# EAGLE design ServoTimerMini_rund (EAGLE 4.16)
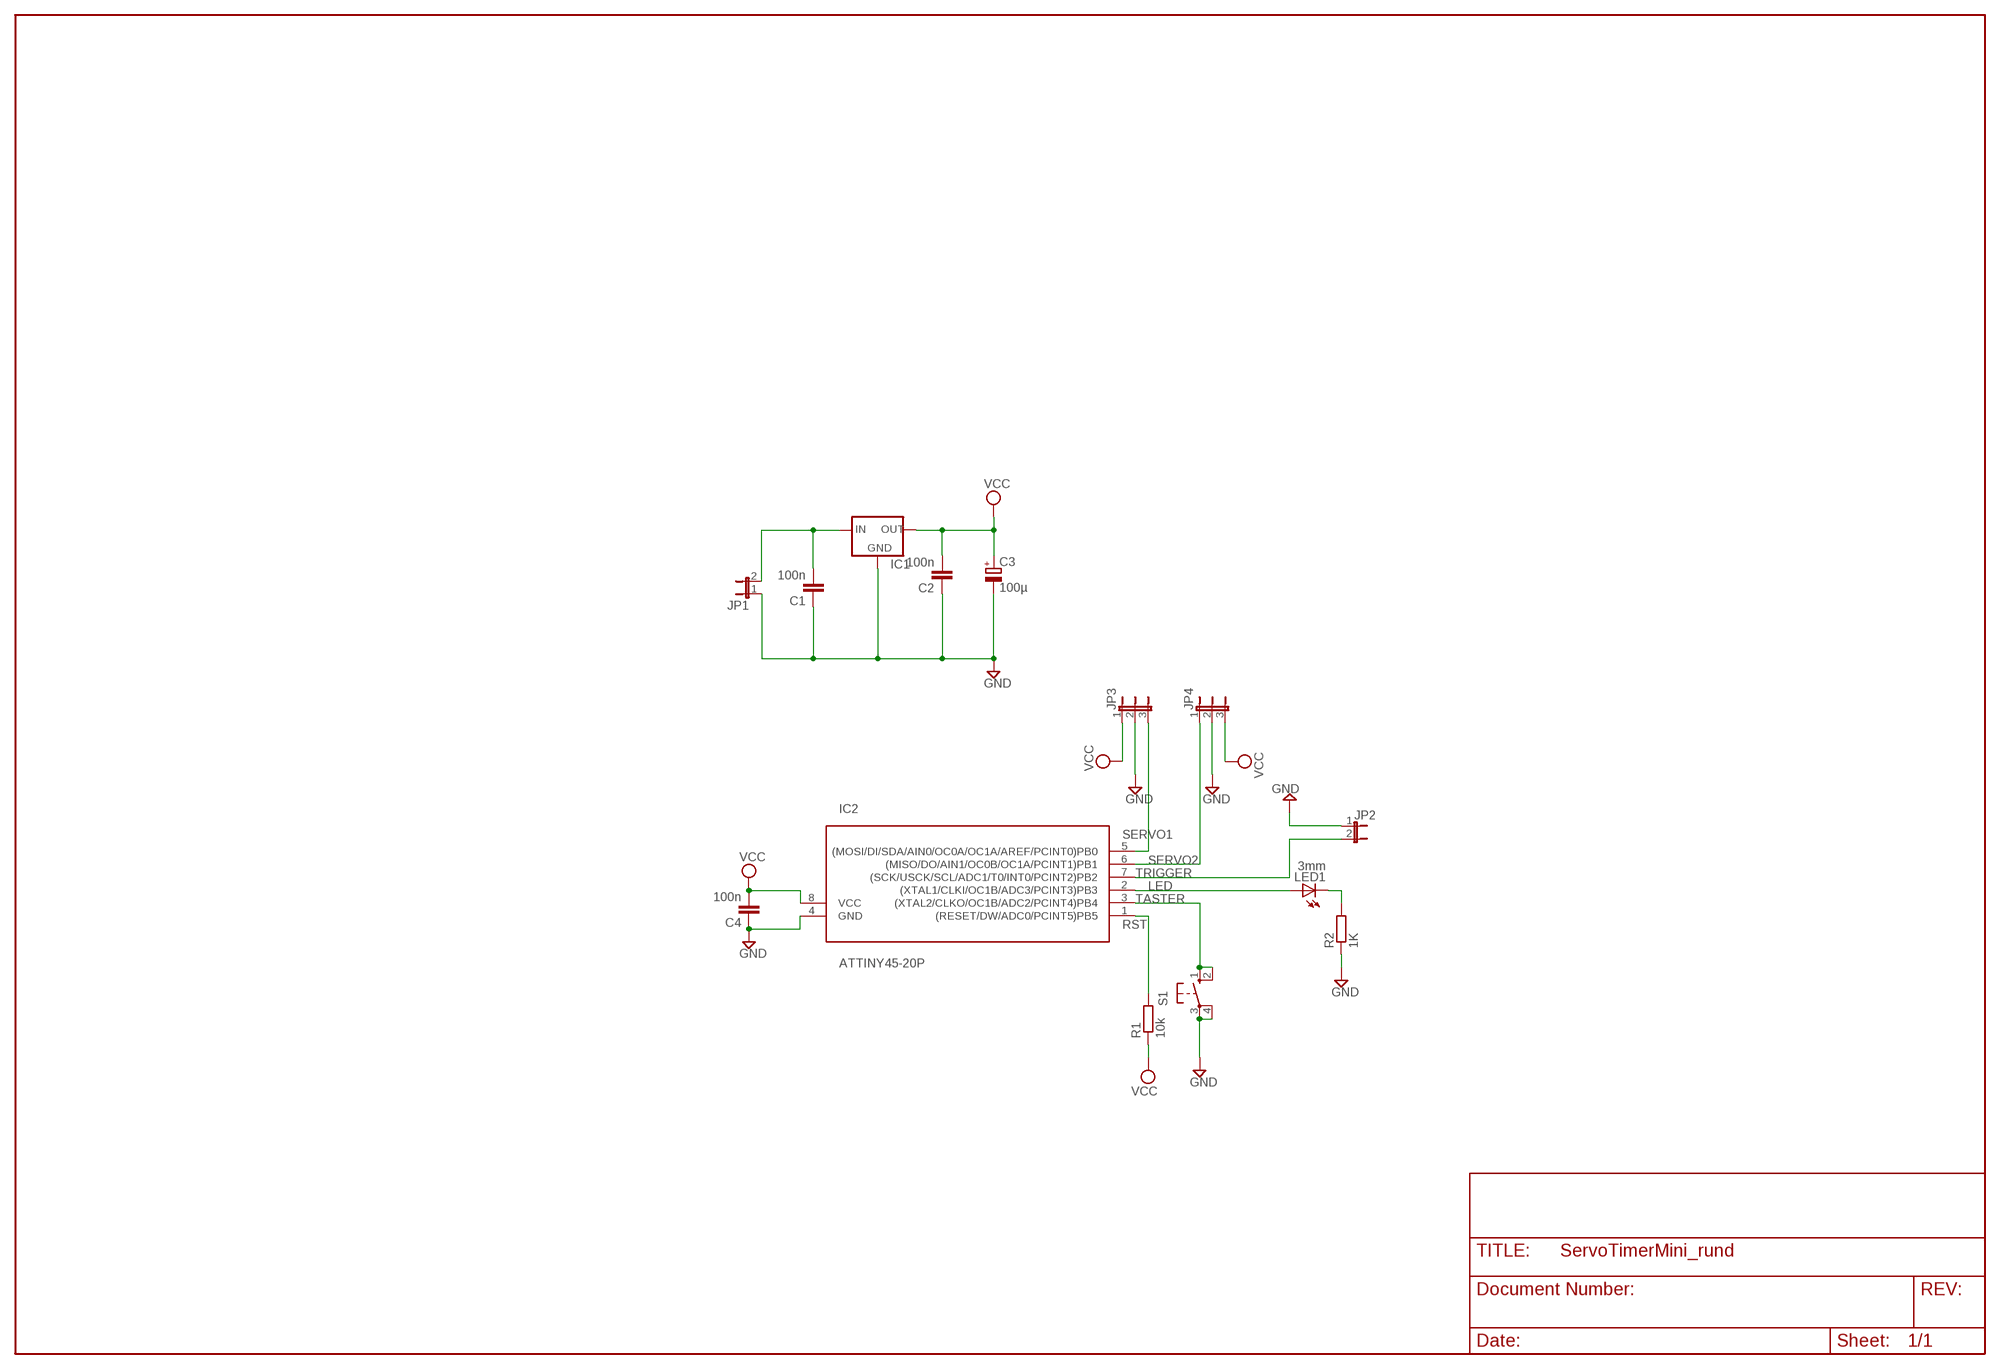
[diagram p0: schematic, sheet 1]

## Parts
C1  100n  C-EU025-025X050  [C025-025X050]
C2  100n  C-EU025-025X050  [C025-025X050]
C3  100µ  CPOL-EUE2.5-6  [E2,5-6]
C4  100n  C-EU025-025X050  [C025-025X050]
IC1  78XXL  [78XXL]
IC2  ATTINY45-20P  [DIL08]
JP1  JP1E  [JP1]
JP2  JP1E  [JP1]
JP3  JP2E  [JP2]
JP4  JP2E  [JP2]
LED1  3mm  LED3MM  [LED3MM]
R1  10k  R-EU_0204/7  [0204/7]
R2  1K  R-EU_0204/7  [0204/7]
S1  10-XX  [B3F-10XX]

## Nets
+9V: C1.2 IC1.IN JP1.2
GND: C1.1 C2.1 C3.- C4.1 IC1.GND IC2.4(GND) JP1.1 JP2.1 JP3.2 JP4.2 R2.1 S1.3(P) S1.4(P1)
LED: IC2.2((XTAL1/CLKI/OC1B/ADC3/PCINT3)PB3) LED1.A
N$4: LED1.K(C) R2.2
RST: IC2.1((RESET/DW/ADC0/PCINT5)PB5) R1.2
SERVO1: IC2.5((MOSI/DI/SDA/AIN0/OC0A/OC1A/AREF/PCINT0)PB0) JP3.3
SERVO2: IC2.6((MISO/DO/AIN1/OC0B/OC1A/PCINT1)PB1) JP4.1
TASTER: IC2.3((XTAL2/CLKO/OC1B/ADC2/PCINT4)PB4) S1.1(S) S1.2(S1)
TRIGGER: IC2.7((SCK/USCK/SCL/ADC1/T0/INT0/PCINT2)PB2) JP2.2
VCC: C2.2 C3.+ C4.2 IC1.OUT IC2.8(VCC) JP3.1 JP4.3 R1.1

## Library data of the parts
C1 C2 C4 = rcl:C-EU: CAPACITOR, European symbol
C3 = rcl:CPOL-EU: POLARIZED CAPACITOR, European symbol
IC1 = v-reg:78XXL: VOLTAGE REGULATOR
IC2 = avr:ATTINY45: MICROCONTROLLER 4 Kbytes FLASH 256 bytes EEPROM 256 bytes RAM 4-channel 10 bit ADC USI
JP1 JP2 = jumper:JP1E: JUMPER
JP3 JP4 = jumper:JP2E: JUMPER
LED1 = led:LED: LED
R1 R2 = rcl:R-EU_: RESISTOR, European symbol
S1 = switch-omron:10-XX: OMRON SWITCH

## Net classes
0 default: width 0.356 mm, drill 0.254 mm, clearance 0.61 mm
1 GND: width 0.991 mm, drill 0.254 mm, clearance 0.61 mm
2 VCC: width 0.356 mm, drill 0.254 mm, clearance 0.61 mm
3 breit2: width 2.032 mm, drill 0.483 mm, clearance 0.61 mm
4 breit3: width 2.54 mm, drill 0.61 mm, clearance 0.61 mm

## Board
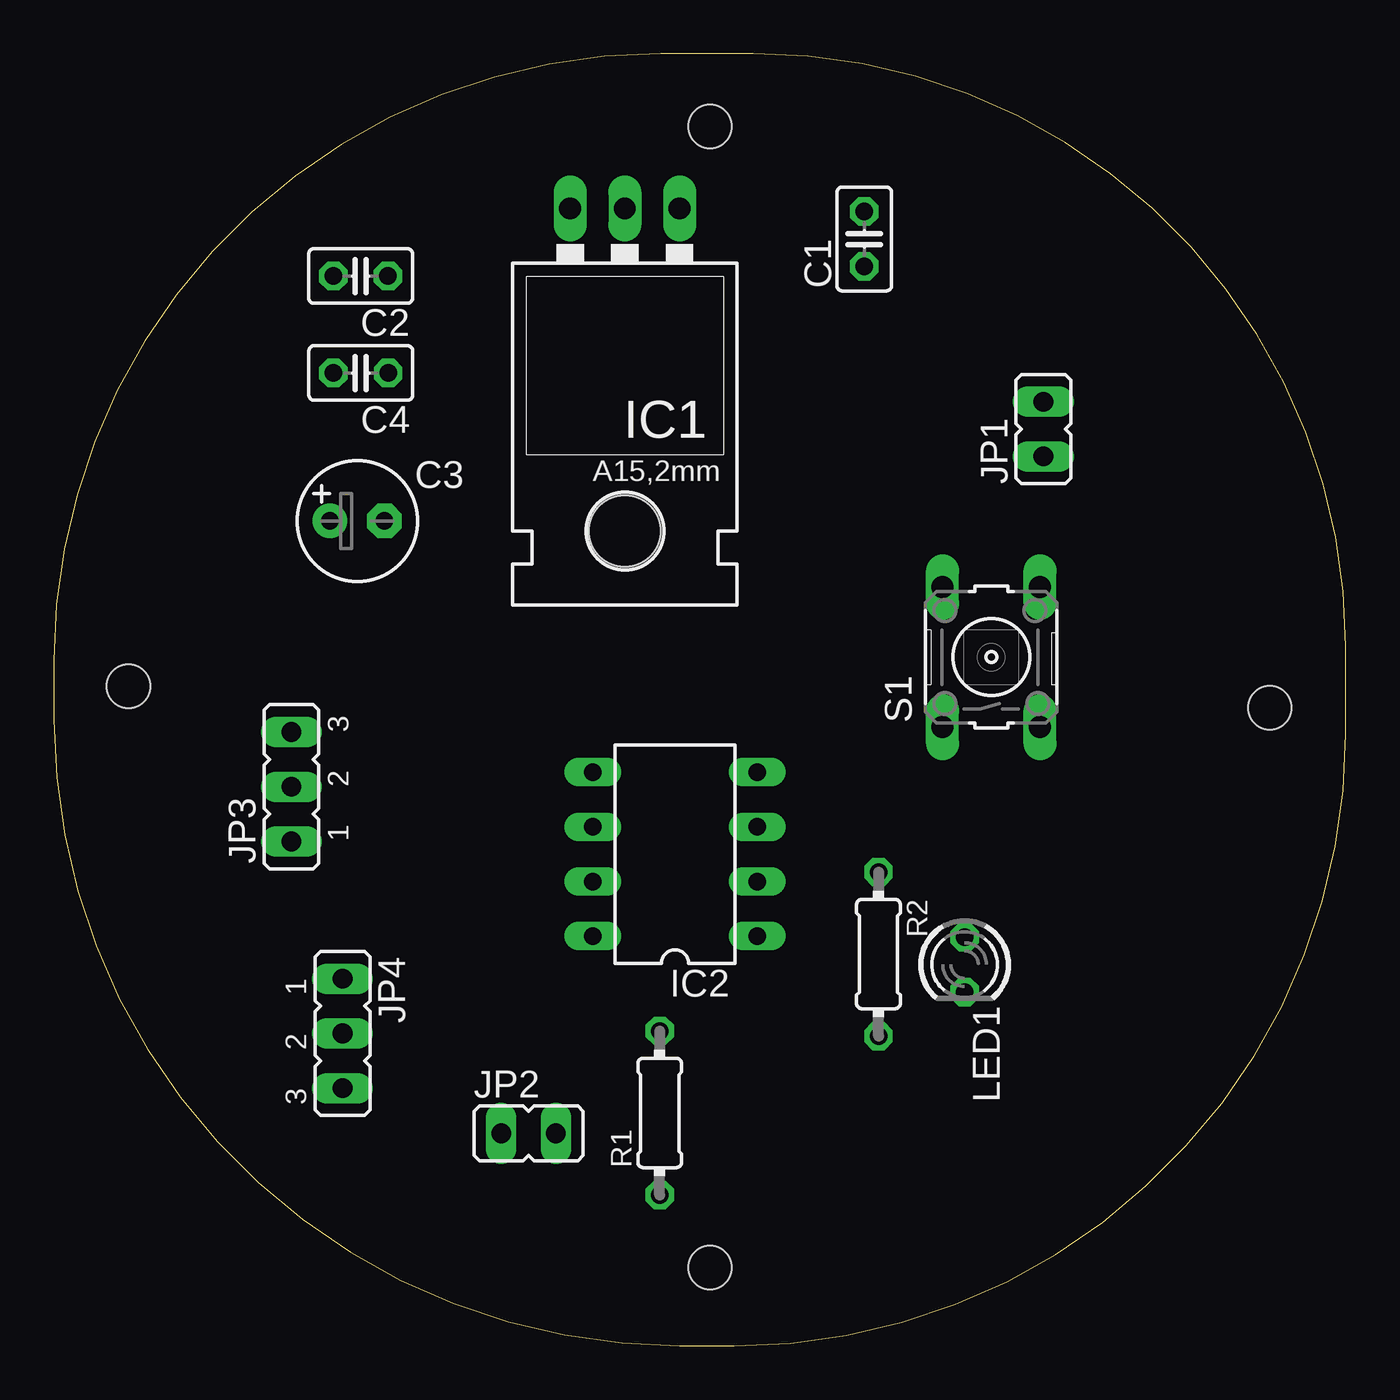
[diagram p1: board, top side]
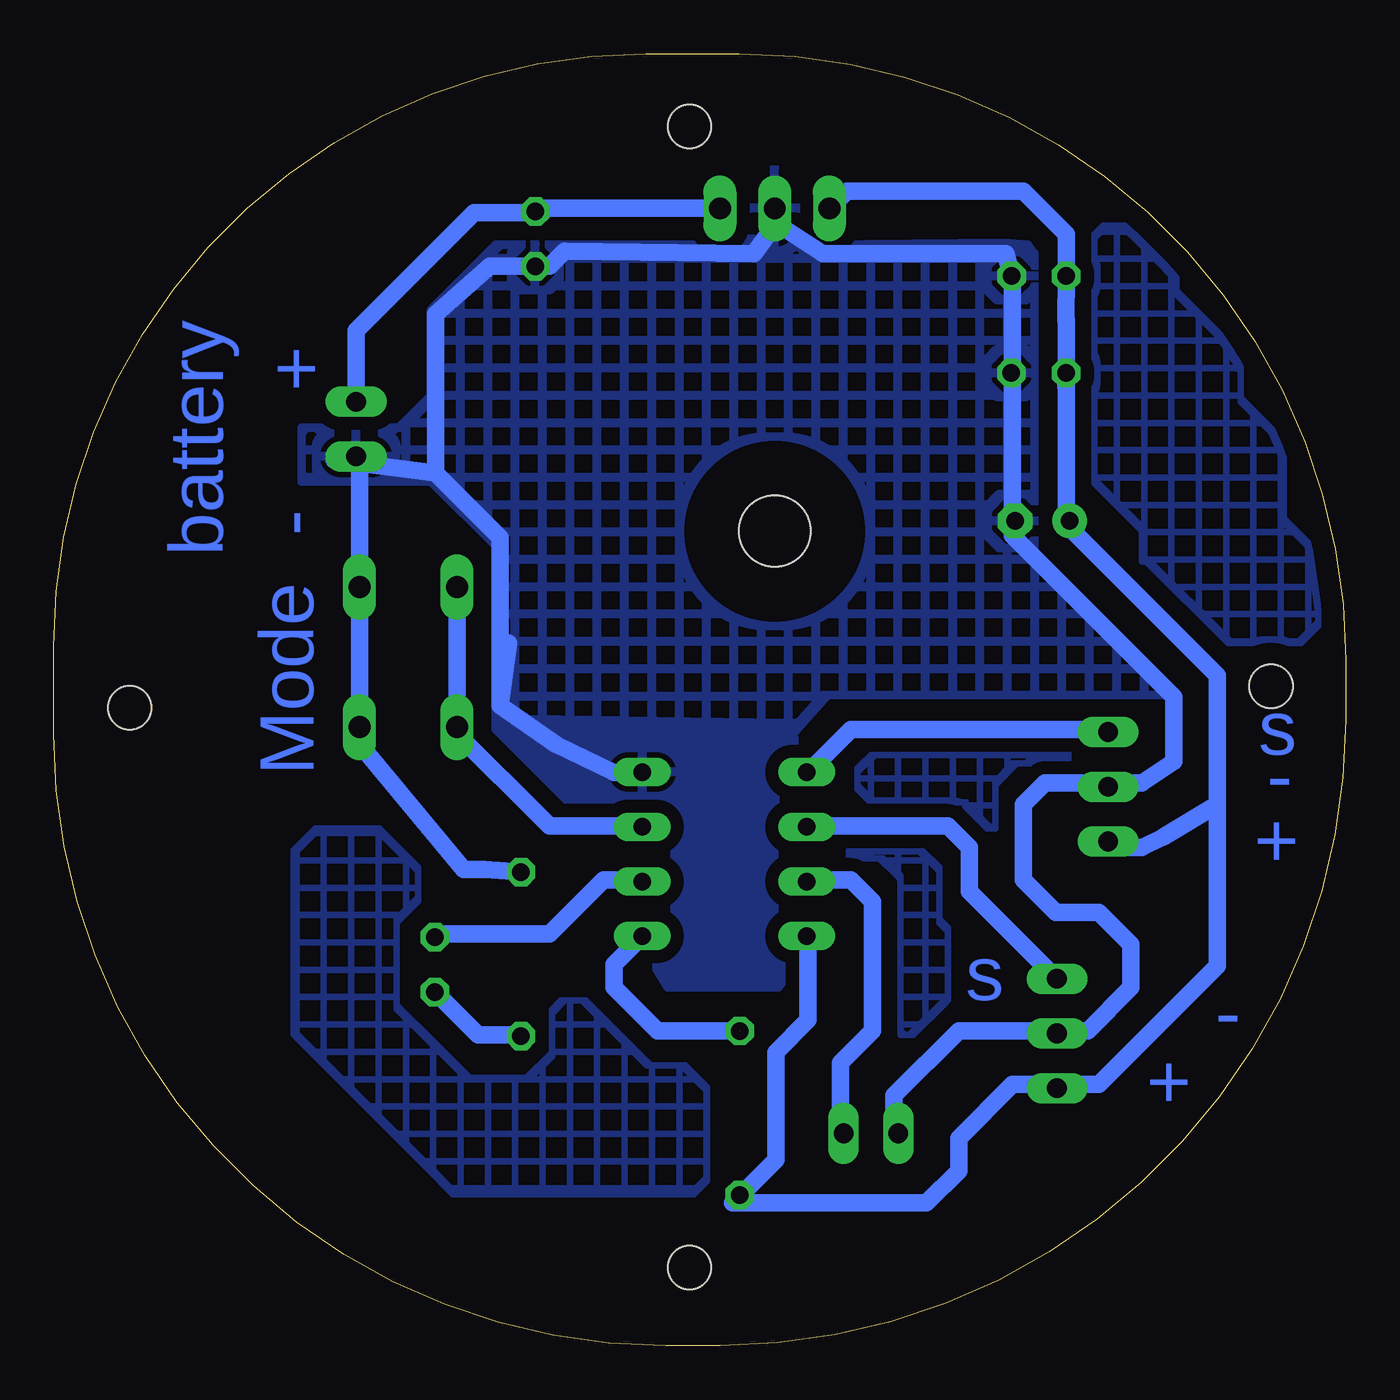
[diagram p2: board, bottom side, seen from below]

Size 60 x 60 mm. Coordinates in mm from the lower left corner, seen from the top.
Outline: 31.59,0 arc90 60,28.41 60,32.49 arc90 32.49,60 28.18,60 arc90 0,31.82 0,29.06 arc90 29.06,0 31.59,0
Copper layers (1*16): Top 0.035mm / dielectric 1.5mm / Bottom 0.035mm
Design rules "default": minimum track width 10mil, minimum drill 24mil, track to track 8mil, track to pad 8mil, pad to pad 8mil, via to via 8mil, smd to smd 8mil, copper to edge 40mil, drill to drill 8mil, minimum pad ring 10mil, minimum via ring 8mil, stop-mask expansion 4mil, vias tented up to drill 0mil, thermal gap 10mil
Holes 2 mm at 56.47,29.63 3.47,30.63 30.47,56.63 30.47,3.63

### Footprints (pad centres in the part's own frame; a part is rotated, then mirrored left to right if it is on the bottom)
C025-025X050 = drill 0.813 octagon: 1 -1.27,0; 2 1.27,0
E2,5-6 = drill 0.813 pad 1.6 round: + -1.27,0 | drill 0.813 pad 1.6 octagon: - 1.27,0
78XXL = drill 1.016 long: GND 0,-3.81; IN -2.54,-3.81; OUT 2.54,-3.81 | hole 3.302: 0,11.176
DIL08 = drill 0.813 long: 1 -3.81,-3.81; 2 -1.27,-3.81; 3 1.27,-3.81; 4 3.81,-3.81; 5 3.81,3.81; 6 1.27,3.81; 7 -1.27,3.81; 8 -3.81,3.81
JP1 = drill 0.914 long: 1 0,-1.27; 2 0,1.27
JP2 = drill 0.914 long: 1 -2.54,0; 2 0,0; 3 2.54,0
LED3MM = drill 0.813 octagon: A -1.27,0; K 1.27,0
0204/7 = drill 0.813 octagon: 1 -3.81,0; 2 3.81,0
B3F-10XX = drill 1.016 long: 1 -3.251,2.261; 2 3.251,2.261; 3 -3.251,-2.261; 4 3.251,-2.261

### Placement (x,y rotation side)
C1  37.64,51.4 90 top
C2  14.25,49.68 180 top
C3  14.09,38.3 0 top
C4  14.26,45.18 180 top
IC1  26.52,49.01 180 top
IC2  28.85,22.83 90 top
JP1  45.96,42.57 0 top
JP2  22.05,9.86 270 top
JP3  11.03,25.96 90 top
JP4  13.41,14.5 270 top
LED1  42.3,17.7 270 top
R1  28.14,10.81 90 top
R2  38.3,18.19 270 top
S1  43.54,31.98 90 top

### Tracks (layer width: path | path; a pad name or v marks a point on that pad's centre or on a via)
+9V
  Bottom 0.813: JP1.2 45.96,47.14 40.47,52.63 37.47,52.63 | 37.47,52.63 37.51,52.67 C1.2 37.6,52.63 37.47,52.63 | IC1.IN 37.28,52.82 37.47,52.63
GND
  Bottom 0.406: 45.87,29.03 46.07,29.03 46.07,28.83 45.87,28.63 45.8,28.7 | 45.8,28.7 45.7,28.8 46.1,28.46 45.97,28.33 45.97,28.13 | S1.3 45.8,28.7
  Bottom 0.813: JP2.1 20.97,10.05 20.97,11.63 17.97,14.63 13.54,14.63 JP4.2 13.47,14.56 13.47,14.63 11.97,14.63 9.97,16.63 9.97,18.63 11.47,20.13 13.47,20.13 14.97,21.63 14.97,25.13 13.97,26.13 11.2,26.13 JP3.2 10.97,26.02 10.97,26.13 9.47,26.13 7.97,27.13 7.97,30.13 15.47,37.63 15.47,38.19 C3.- 15.47,38.41 15.47,45.13 15.48,45.13 C4.1 15.47,45.23 15.47,49.63 C2.1 15.77,50.73 24.27,50.73 26.47,52.13 | IC1.GND 26.47,52.77 26.47,52.13 | 26.47,52.13 27.47,50.73 36.27,50.83 36.97,50.13 C1.1 39.77,50.13 39.87,50.03 42.27,47.9 42.27,40.53 | 42.27,40.53 46.97,41.13 | IC2.4 33.97,26.63 36.67,27.93 39.27,29.73 | 39.27,29.73 39.27,37.53 42.27,40.53 | R2.1 40.01,22.13 40.97,22.13 45.97,28.13 | 46.97,41.13 JP1.1 45.96,41.14 46.97,41.13 | 46.97,41.13 45.8,40.96 S1.4 45.57,35.23 45.47,35.13 45.8,34.8 S1.3 45.57,28.73 45.47,28.63 | 45.87,29.03 45.8,28.96 | 39.27,29.73 38.87,32.63 39.11,31.99 39.27,31.99
  pour Bottom (hatched): 39.47,28.63 39.47,37.13 42.47,40.13 48.47,40.13 48.47,42.63 43.97,42.63 42.47,44.13 42.47,48.13 39.47,51.13 28.97,51.13 28.97,54.63 24.47,54.63 24.47,51.13 15.87,51.23 14.77,51.13 14.47,50.73 14.47,36.83 7.87,30.23 24.07,30.23 25.57,28.53 39.47,29.13
  pour Bottom: 25.57,28.13 25.57,17.63 26.37,16.63 31.47,16.63 32.07,17.63 32.07,24.63 33.17,25.33 36.17,25.33 39.47,28.63 39.47,29.13 25.97,28.93
LED
  Bottom 0.813: IC2.2 32.73,21.63 34.47,21.63 36.97,19.13 42.46,19.13 | 42.46,19.13 42.47,19.13 | 42.46,19.13 LED1.A
N$1
  pour Bottom (isolate 0.61, hatched): 12.87,27.63 21.87,27.63 22.67,26.83 22.67,25.83 22.07,25.23 17.67,25.23 17.67,25.03 16.67,24.03 16.27,24.03 16.27,25.63 16.27,26.03 15.27,27.03 13.07,27.03 12.87,27.23
N$2
  pour Bottom (isolate 0.61, hatched): 23.07,23.03 19.87,23.03 19.67,23.03 18.87,22.23 18.87,20.43 18.87,19.83 18.47,19.43 18.47,16.03 18.67,15.83 20.07,14.43 20.67,14.43 20.67,21.63 20.87,21.83 21.67,22.63 23.07,22.63 23.07,22.83
N$3
  pour Bottom (isolate 0.61, hatched): 35.27,16.03 33.07,13.83 32.27,13.03 30.67,13.03 30.27,12.63 29.67,12.03 29.67,7.63 30.27,7.03 41.47,7.03 42.67,8.23 48.87,14.43 48.87,23.03 47.87,24.03 45.07,24.03 44.87,24.03 43.07,22.23 43.07,20.63 44.07,19.63 44.07,15.83 42.27,14.03 40.67,12.43 38.07,12.43 36.87,13.63 36.87,15.23 36.87,15.63 36.47,16.03
N$4
  Bottom 0.813: LED1.K 40.3,14.43 38.27,14.43 38.27,14.38 R2.2
N$5
  pour Bottom (isolate 0.61, hatched): 5.07,32.63 2.27,32.63 2.07,32.63 1.27,33.43 1.27,36.83 1.67,37.23 2.87,38.43 2.87,41.83 3.07,42.03 3.07,42.23 4.87,44.03 4.87,46.03 6.27,47.43 7.87,49.03 7.87,50.23 8.27,50.63 9.67,52.03 10.87,52.03 11.27,52.03 11.67,51.63 11.67,40.23 11.67,40.03 9.47,37.83 9.47,36.43 9.27,36.43 5.47,32.63
RST  (1 unrouted)
  Bottom 0.406: 31.07,14.63 31.07,14.48 31.07,14.43
  Bottom 0.813: IC2.1 33.97,17.71 33.97,16.63 31.97,14.63 31.07,14.63 R1.2 27.97,14.63
SERVO1
  Bottom 0.813: JP3.3 11.16,28.63 22.97,28.63 24.97,26.63 IC2.5
SERVO2
  Bottom 0.813: JP4.1 17.47,21.1 17.47,23.13 18.47,24.13 25.01,24.13 IC2.6
TASTER
  Bottom 0.813: IC2.3 32.69,24.13 36.97,24.13 41.47,28.63 41.37,28.73 S1.1 41.28,35.44 | 41.28,35.44 S1.2 | 41.28,35.44 41.47,35.63
TRIGGER
  Bottom 0.813: IC2.7 24.97,21.63 22.97,21.63 21.97,20.63 21.97,14.63 23.47,13.13 23.47,10.01 JP2.2
VCC
  Bottom 0.813: IC1.OUT 23.17,53.63 14.97,53.63 12.97,51.63 C2.2 | C2.2 | C2.2 12.99,47.63 12.97,47.63 12.97,43.69 C4.2 12.97,45.16 12.97,38.15 | 12.97,38.15 12.97,38.13 5.97,31.13 5.97,25.13 | 12.97,38.15 C3.+ | 5.97,25.13 8.47,23.63 9.47,23.13 10.97,23.13 10.97,23.36 JP3.1 | 5.97,25.13 5.97,17.63 11.47,12.13 13.24,12.13 JP4.3 13.58,12.13 15.47,12.13 17.97,9.63 17.97,8.13 19.47,6.63 28.47,6.63 27.97,7.13 | IC2.8 24.97,18.95 24.97,15.13 26.47,13.63 26.47,8.63 27.97,7.13 | R1.1 28.01,7.13 27.97,7.13

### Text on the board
Bottom: battery | + | - | Mode | s | - | + | s | - | +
